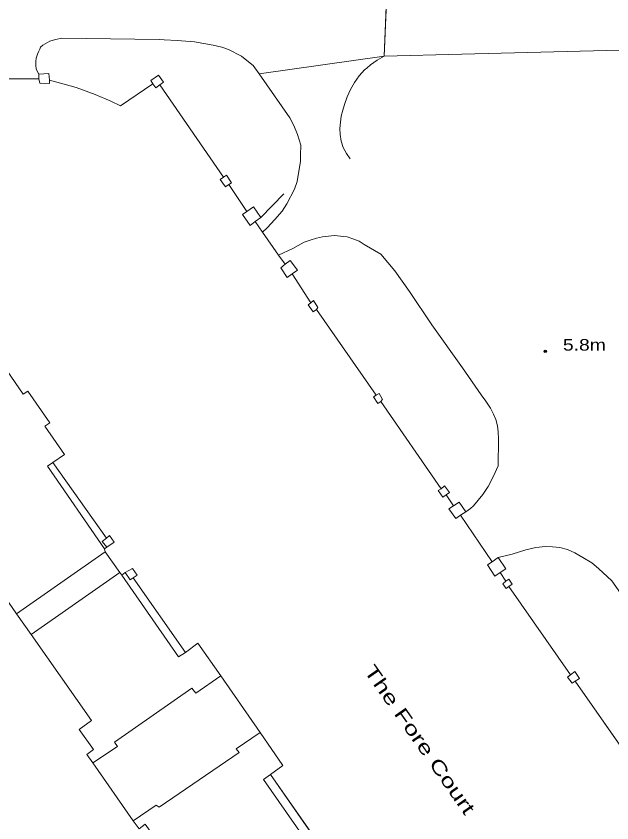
# Model space of a CAD drawing. Extents: x 528790 to 529292, y 179350 to 179856.
# Drawn here: x 529045.4 to 529122.8, y 179668.3 to 179772.9 of the extents above; entities that cross this region are included whole.
import ezdxf

# ---------------------------------------------------------------- set-up
doc = ezdxf.new("R2010")
doc.units = 0
doc.header["$LTSCALE"] = 0.6
doc.header["$PDMODE"] = 32
doc.header["$PDSIZE"] = 0.3
doc.layers.add('1', color=7, linetype='Continuous', lineweight=13)
doc.layers.add('2', color=7, linetype='Continuous', lineweight=13)
doc.layers.add('3', color=7, linetype='Continuous')
doc.layers.add('5', color=7, linetype='Continuous')

msp = doc.modelspace()

# ---------------------------------------------------------------- linework, layer by layer
at = {"layer": '1'}
for points in [[(529093.884, 179783.837), (529093.19, 179767.75), (529103.296, 179768.007), (529128.896, 179768.657), (529142.81, 179769.01), (529140.75, 179788.25)], [(529044.2, 179764.8), (529048.4, 179764.8), (529048.4, 179765.4), (529048.2, 179765.7), (529048.05, 179766.1), (529048, 179766.55), (529048, 179767.05), (529048.05, 179767.5), (529048.2, 179768), (529048.35, 179768.3), (529048.5, 179768.65), (529048.6, 179768.9), (529048.9, 179769.2), (529049.8, 179769.7), (529050.55, 179769.9), (529051.35, 179770.1), (529064, 179769.9), (529064.665, 179769.872), (529066.35, 179769.8), (529068.6, 179769.6), (529071, 179769.2), (529072.15, 179768.9), (529073, 179768.6), (529074.7, 179767.75), (529075.4, 179767.2), (529076.2, 179766.55), (529076.96, 179765.46), (529093.19, 179767.75), (529093.884, 179783.837)], [(529128.896, 179768.657), (529103.296, 179768.007), (529093.19, 179767.75), (529076.96, 179765.46), (529080.95, 179759.75), (529081.5, 179758.75), (529081.95, 179757.6), (529082.4, 179756.2), (529082.35, 179754.9), (529082.35, 179754.388), (529082.35, 179754.1), (529082.05, 179752.3), (529081.9, 179751.5), (529081.55, 179750.5), (529080.55, 179748.6), (529079.95, 179747.65), (529079, 179746.55), (529078, 179745.5), (529077.4, 179744.9), (529079.5, 179741.95), (529081.35, 179742.8), (529082.05, 179743.2), (529082.8, 179743.6), (529083.6, 179743.9), (529084.4, 179744.15), (529085.2, 179744.3), (529086, 179744.4), (529086.75, 179744.5), (529087.55, 179744.4), (529088.4, 179744.3), (529089.15, 179744.05), (529089.95, 179743.75), (529090.6, 179743.3), (529092.75, 179742.05), (529094.6, 179739.9), (529096.5, 179737.2), (529099.4, 179732.9), (529103.35, 179727.3), (529105.8, 179723.8), (529106.4, 179723), (529107, 179722.1), (529107.4, 179721.3), (529107.7, 179720.6), (529107.9, 179719.8), (529108, 179719), (529108.05, 179718.05), (529108, 179714.6), (529107.4, 179713.25), (529106.7, 179711.9), (529106, 179710.9), (529104.8, 179709.4), (529104.4, 179709.05), (529103.8, 179708.65), (529103.1, 179708.2), (529107.2, 179702.15), (529108, 179702.7), (529109.8, 179703.15), (529111.6, 179703.7), (529112.9, 179704), (529114.15, 179704.15), (529115.05, 179704.1), (529116, 179704), (529117, 179703.75), (529117.95, 179703.3), (529119, 179702.7), (529120.15, 179702), (529121, 179701.3), (529122.75, 179699.7), (529130.88, 179688.08)], [(529055.7, 179762.8), (529053.25, 179763.7), (529051.2, 179764.25), (529049.75, 179764.65), (529049.75, 179764.2), (529048.5, 179764.25), (529048.4, 179764.8), (529044.2, 179764.8)], [(529125.85, 179675.4), (529118, 179686.65), (529117.6, 179686.4), (529117, 179687.2), (529117.4, 179687.5), (529109.4, 179698.95), (529109.05, 179698.7), (529108.6, 179699.3), (529109, 179699.65), (529108.25, 179700.75), (529107.55, 179700.3), (529106.6, 179701.75), (529107.2, 179702.15), (529103.1, 179708.2), (529102.5, 179707.75), (529101.6, 179709), (529102.2, 179709.4), (529101.25, 179710.85), (529100.8, 179710.55), (529100.2, 179711.4), (529100.6, 179711.6), (529092.75, 179722.95), (529092.4, 179722.7), (529091.8, 179723.55), (529092.15, 179723.75), (529084.4, 179734.9), (529084, 179734.6), (529083.35, 179735.5), (529083.7, 179735.75), (529081.25, 179739.5), (529080.6, 179739.05), (529079.8, 179740.3), (529080.35, 179740.75), (529079.5, 179741.95), (529077.4, 179744.9), (529076.45, 179746.3), (529075.8, 179745.8), (529074.8, 179747.2), (529075.4, 179747.6), (529073.05, 179751.1), (529072.6, 179750.8), (529071.9, 179751.75), (529072.35, 179752.05), (529064.1, 179764.05), (529063.55, 179763.65), (529063.2, 179764.15), (529059, 179761.3), (529057.75, 179761.9), (529055.7, 179762.8)], [(529039.6, 179703.9), (529045.5, 179695.4), (529057, 179703.45), (529056.9, 179703.85), (529049.5, 179714.55), (529050.2, 179715.05), (529051.7, 179716.05), (529049.15, 179719.75), (529049.8, 179720.2), (529046.95, 179724.3), (529046.35, 179723.9), (529043.7, 179727.75)], [(529043.7, 179727.75), (529046.35, 179723.9), (529046.95, 179724.3), (529049.8, 179720.2), (529049.15, 179719.75), (529051.7, 179716.05), (529050.2, 179715.05), (529057.15, 179705.2), (529057.55, 179705.55), (529058.15, 179704.7), (529057.2, 179704.05), (529056.9, 179703.85), (529057, 179703.45), (529058.9, 179700.75), (529059.15, 179700.4), (529059.6, 179700.75), (529060.55, 179701.3), (529061.15, 179700.4), (529060.65, 179700.05), (529067.4, 179690.4), (529069, 179691.6), (529072, 179687.35), (529077.1, 179680), (529080.05, 179675.7), (529078.45, 179674.55), (529085.2, 179664.9)], [(529061.4, 179667.5), (529060.65, 179668.55), (529055.4, 179676.05), (529054.6, 179677.15), (529055.5, 179677.8), (529053.6, 179680.4), (529055.2, 179681.55), (529047.4, 179692.7), (529045.5, 179695.4), (529039.6, 179703.9)], [(529130.88, 179688.08), (529122.75, 179699.7), (529121, 179701.3), (529120.15, 179702), (529119, 179702.7), (529117.95, 179703.3), (529117, 179703.75), (529116, 179704), (529115.05, 179704.1), (529114.15, 179704.15), (529112.9, 179704), (529111.6, 179703.7), (529109.8, 179703.15), (529108, 179702.7), (529109, 179701.25), (529108.25, 179700.75), (529109, 179699.65), (529109.4, 179699.9), (529109.8, 179699.25), (529109.4, 179698.95), (529117.4, 179687.5), (529117.95, 179687.9), (529118.55, 179687), (529118, 179686.65), (529125.85, 179675.4)]]:
    msp.add_lwpolyline(points, dxfattribs=at)
for points in [[(529076.96, 179765.46), (529076.2, 179766.55), (529075.4, 179767.2), (529074.7, 179767.75), (529073, 179768.6), (529072.15, 179768.9), (529071, 179769.2), (529068.6, 179769.6), (529066.35, 179769.8), (529064.665, 179769.872), (529064, 179769.9), (529051.35, 179770.1), (529050.55, 179769.9), (529049.8, 179769.7), (529048.9, 179769.2), (529048.6, 179768.9), (529048.5, 179768.65), (529048.35, 179768.3), (529048.2, 179768), (529048.05, 179767.5), (529048, 179767.05), (529048, 179766.55), (529048.05, 179766.1), (529048.2, 179765.7), (529048.4, 179765.4), (529049.7, 179765.5), (529049.75, 179764.65), (529051.2, 179764.25), (529053.25, 179763.7), (529055.7, 179762.8), (529057.75, 179761.9), (529059, 179761.3), (529063.2, 179764.15), (529062.9, 179764.6), (529063.9, 179765.3), (529064.55, 179764.4), (529064.1, 179764.05), (529072.35, 179752.05), (529072.75, 179752.3), (529073.4, 179751.3), (529073.05, 179751.1), (529075.4, 179747.6), (529076.25, 179748.2), (529077.2, 179746.8), (529076.45, 179746.3), (529077.4, 179744.9), (529078, 179745.5), (529079, 179746.55), (529079.95, 179747.65), (529080.55, 179748.6), (529081.55, 179750.5), (529081.9, 179751.5), (529082.05, 179752.3), (529082.35, 179754.1), (529082.35, 179754.388), (529082.35, 179754.9), (529082.4, 179756.2), (529081.95, 179757.6), (529081.5, 179758.75), (529080.95, 179759.75)], [(529049.75, 179764.65), (529049.7, 179765.5), (529048.4, 179765.4), (529048.4, 179764.8), (529048.5, 179764.25), (529049.75, 179764.2)], [(529064.1, 179764.05), (529064.55, 179764.4), (529063.9, 179765.3), (529062.9, 179764.6), (529063.2, 179764.15), (529063.55, 179763.65)], [(529073.05, 179751.1), (529073.4, 179751.3), (529072.75, 179752.3), (529072.35, 179752.05), (529071.9, 179751.75), (529072.6, 179750.8)], [(529076.45, 179746.3), (529077.2, 179746.8), (529076.25, 179748.2), (529075.4, 179747.6), (529074.8, 179747.2), (529075.8, 179745.8)], [(529083.7, 179735.75), (529084.05, 179736.05), (529084.6, 179735.15), (529084.4, 179734.9), (529092.15, 179723.75), (529092.55, 179724), (529093, 179723.2), (529092.75, 179722.95), (529100.6, 179711.6), (529101.05, 179712), (529101.7, 179711.15), (529101.25, 179710.85), (529102.2, 179709.4), (529102.95, 179709.9), (529103.8, 179708.65), (529104.4, 179709.05), (529104.8, 179709.4), (529106, 179710.9), (529106.7, 179711.9), (529107.4, 179713.25), (529108, 179714.6), (529108.05, 179718.05), (529108, 179719), (529107.9, 179719.8), (529107.7, 179720.6), (529107.4, 179721.3), (529107, 179722.1), (529106.4, 179723), (529105.8, 179723.8), (529103.35, 179727.3), (529099.4, 179732.9), (529096.5, 179737.2), (529094.6, 179739.9), (529092.75, 179742.05), (529090.6, 179743.3), (529089.95, 179743.75), (529089.15, 179744.05), (529088.4, 179744.3), (529087.55, 179744.4), (529086.75, 179744.5), (529086, 179744.4), (529085.2, 179744.3), (529084.4, 179744.15), (529083.6, 179743.9), (529082.8, 179743.6), (529082.05, 179743.2), (529081.35, 179742.8), (529079.5, 179741.95), (529080.35, 179740.75), (529081, 179741.25), (529081.95, 179740), (529081.25, 179739.5)], [(529081.25, 179739.5), (529081.95, 179740), (529081, 179741.25), (529080.35, 179740.75), (529079.8, 179740.3), (529080.6, 179739.05)], [(529084.4, 179734.9), (529084.6, 179735.15), (529084.05, 179736.05), (529083.7, 179735.75), (529083.35, 179735.5), (529084, 179734.6)], [(529092.75, 179722.95), (529093, 179723.2), (529092.55, 179724), (529092.15, 179723.75), (529091.8, 179723.55), (529092.4, 179722.7)], [(529056.9, 179703.85), (529057.2, 179704.05), (529056.6, 179704.8), (529057.15, 179705.2), (529050.2, 179715.05), (529049.5, 179714.55)], [(529101.25, 179710.85), (529101.7, 179711.15), (529101.05, 179712), (529100.6, 179711.6), (529100.2, 179711.4), (529100.8, 179710.55)], [(529103.1, 179708.2), (529103.8, 179708.65), (529102.95, 179709.9), (529102.2, 179709.4), (529101.6, 179709), (529102.5, 179707.75)], [(529057.15, 179705.2), (529056.6, 179704.8), (529057.2, 179704.05), (529058.15, 179704.7), (529057.55, 179705.55)], [(529045.5, 179695.4), (529047.4, 179692.7), (529058.9, 179700.75), (529057, 179703.45)], [(529108.25, 179700.75), (529109, 179701.25), (529108, 179702.7), (529107.2, 179702.15), (529106.6, 179701.75), (529107.55, 179700.3)], [(529047.4, 179692.7), (529055.2, 179681.55), (529053.6, 179680.4), (529055.5, 179677.8), (529054.6, 179677.15), (529055.4, 179676.05), (529058.6, 179678.2), (529058.2, 179678.75), (529068.25, 179685.75), (529068.75, 179685.1), (529072, 179687.35), (529069, 179691.6), (529067.4, 179690.4), (529066.5, 179689.8), (529059.15, 179700.4), (529058.9, 179700.75)], [(529059.15, 179700.4), (529066.5, 179689.8), (529067.4, 179690.4), (529060.65, 179700.05), (529060.25, 179699.8), (529059.6, 179700.75)], [(529060.65, 179700.05), (529061.15, 179700.4), (529060.55, 179701.3), (529059.6, 179700.75), (529060.25, 179699.8)], [(529109.4, 179698.95), (529109.8, 179699.25), (529109.4, 179699.9), (529109, 179699.65), (529108.6, 179699.3), (529109.05, 179698.7)], [(529072, 179687.35), (529068.75, 179685.1), (529068.25, 179685.75), (529058.2, 179678.75), (529058.6, 179678.2), (529055.4, 179676.05), (529060.65, 179668.55), (529063.6, 179670.55), (529064, 179670.3), (529074.4, 179677.4), (529074, 179677.9), (529077.1, 179680)], [(529118, 179686.65), (529118.55, 179687), (529117.95, 179687.9), (529117.4, 179687.5), (529117, 179687.2), (529117.6, 179686.4)], [(529084.8, 179663.5), (529077.55, 179673.9), (529078.45, 179674.55), (529080.05, 179675.7), (529077.1, 179680), (529074, 179677.9), (529074.4, 179677.4), (529064, 179670.3), (529063.6, 179670.55), (529060.65, 179668.55), (529061.4, 179667.5), (529062.2, 179668.1), (529064.2, 179665.25), (529065.8, 179666.3), (529073.7, 179655.05), (529085.05, 179663.1)], [(529078.45, 179674.55), (529077.55, 179673.9), (529084.8, 179663.5), (529085.35, 179663.9), (529084.8, 179664.65), (529085.2, 179664.9)]]:
    msp.add_lwpolyline(points, close=True, dxfattribs=at)
at = {"layer": '2'}
for p, q in [((529093.19, 179767.75), (529093.884, 179783.837)), ((529093.19, 179767.75), (529076.96, 179765.46)), ((529044.2, 179764.8), (529048.4, 179764.8)), ((529048.4, 179764.8), (529048.4, 179765.4)), ((529064.1, 179764.05), (529072.35, 179752.05)), ((529073.05, 179751.1), (529075.4, 179747.6)), ((529077.2, 179746.8), (529080.164, 179749.87)), ((529076.45, 179746.3), (529077.2, 179746.8)), ((529076.45, 179746.3), (529077.4, 179744.9)), ((529077.4, 179744.9), (529079.5, 179741.95)), ((529079.5, 179741.95), (529080.35, 179740.75)), ((529081.25, 179739.5), (529083.7, 179735.75)), ((529084.4, 179734.9), (529092.15, 179723.75)), ((529092.75, 179722.95), (529100.6, 179711.6)), ((529050.2, 179715.05), (529057.15, 179705.2)), ((529101.25, 179710.85), (529102.2, 179709.4)), ((529103.8, 179708.65), (529103.1, 179708.2)), ((529103.1, 179708.2), (529107.2, 179702.15)), ((529057.2, 179704.05), (529056.9, 179703.85)), ((529056.9, 179703.85), (529057, 179703.45)), ((529045.5, 179695.4), (529057, 179703.45)), ((529057, 179703.45), (529058.9, 179700.75)), ((529107.2, 179702.15), (529108, 179702.7)), ((529047.4, 179692.7), (529058.9, 179700.75)), ((529058.9, 179700.75), (529059.15, 179700.4)), ((529059.6, 179700.75), (529059.15, 179700.4)), ((529108.25, 179700.75), (529109, 179699.65)), ((529067.4, 179690.4), (529060.65, 179700.05)), ((529109.4, 179698.95), (529117.4, 179687.5)), ((529047.4, 179692.7), (529045.5, 179695.4)), ((529072, 179687.35), (529077.1, 179680)), ((529118, 179686.65), (529125.85, 179675.4)), ((529060.65, 179668.55), (529055.4, 179676.05)), ((529078.45, 179674.55), (529085.2, 179664.9))]:
    msp.add_line(p, q, dxfattribs=at)
for points in [[(529048.4, 179765.4), (529048.2, 179765.7), (529048.05, 179766.1), (529048, 179766.55), (529048, 179767.05), (529048.05, 179767.5), (529048.2, 179768), (529048.35, 179768.3), (529048.5, 179768.65), (529048.6, 179768.9), (529048.9, 179769.2), (529049.8, 179769.7), (529050.55, 179769.9), (529051.35, 179770.1), (529064, 179769.9), (529064.665, 179769.872)], [(529064.665, 179769.872), (529066.35, 179769.8), (529068.6, 179769.6), (529071, 179769.2), (529072.15, 179768.9), (529073, 179768.6), (529074.7, 179767.75), (529075.4, 179767.2), (529076.2, 179766.55), (529076.96, 179765.46)], [(529142.81, 179769.01), (529128.896, 179768.657), (529103.296, 179768.007), (529093.19, 179767.75)], [(529088.79, 179754.43), (529088.3, 179755.14), (529087.9, 179755.91), (529087.62, 179756.74), (529087.48, 179757.58), (529087.46, 179758.38), (529087.52, 179759.17), (529087.64, 179759.96), (529087.82, 179760.74), (529088.05, 179761.5), (529088.41, 179762.48), (529088.85, 179763.43), (529089.37, 179764.34), (529089.97, 179765.2), (529090.66, 179765.96), (529090.95, 179766.21), (529091.44, 179766.65), (529092.29, 179767.25), (529093.19, 179767.75)], [(529048.4, 179765.4), (529049.7, 179765.5), (529049.75, 179764.65)], [(529049.75, 179764.65), (529049.75, 179764.2), (529048.5, 179764.25), (529048.4, 179764.8)], [(529049.75, 179764.65), (529051.2, 179764.25), (529053.25, 179763.7), (529055.7, 179762.8), (529057.75, 179761.9), (529059, 179761.3), (529063.2, 179764.15)], [(529063.2, 179764.15), (529062.9, 179764.6), (529063.9, 179765.3), (529064.55, 179764.4), (529064.1, 179764.05)], [(529076.96, 179765.46), (529080.95, 179759.75), (529081.5, 179758.75), (529081.95, 179757.6), (529082.4, 179756.2), (529082.35, 179754.9), (529082.35, 179754.388)], [(529064.1, 179764.05), (529063.55, 179763.65), (529063.2, 179764.15)], [(529082.35, 179754.388), (529082.35, 179754.1), (529082.05, 179752.3), (529081.9, 179751.5), (529081.55, 179750.5), (529080.55, 179748.6), (529079.95, 179747.65), (529079, 179746.55), (529078, 179745.5), (529077.4, 179744.9)], [(529073.05, 179751.1), (529072.6, 179750.8), (529071.9, 179751.75), (529072.35, 179752.05)], [(529073.05, 179751.1), (529073.4, 179751.3), (529072.75, 179752.3), (529072.35, 179752.05)], [(529077.2, 179746.8), (529076.25, 179748.2), (529075.4, 179747.6)], [(529076.45, 179746.3), (529075.8, 179745.8), (529074.8, 179747.2), (529075.4, 179747.6)], [(529079.5, 179741.95), (529081.35, 179742.8), (529082.05, 179743.2), (529082.8, 179743.6), (529083.6, 179743.9), (529084.4, 179744.15), (529085.2, 179744.3), (529086, 179744.4), (529086.75, 179744.5), (529087.55, 179744.4), (529088.4, 179744.3), (529089.15, 179744.05), (529089.95, 179743.75), (529090.6, 179743.3), (529092.75, 179742.05), (529094.6, 179739.9), (529096.5, 179737.2), (529099.4, 179732.9), (529103.35, 179727.3), (529105.8, 179723.8), (529106.4, 179723), (529107, 179722.1), (529107.4, 179721.3), (529107.7, 179720.6), (529107.9, 179719.8), (529108, 179719), (529108.05, 179718.05), (529108, 179714.6), (529107.4, 179713.25), (529106.7, 179711.9), (529106, 179710.9), (529104.8, 179709.4), (529104.4, 179709.05), (529103.8, 179708.65)], [(529081.25, 179739.5), (529080.6, 179739.05), (529079.8, 179740.3), (529080.35, 179740.75)], [(529081.25, 179739.5), (529081.95, 179740), (529081, 179741.25), (529080.35, 179740.75)], [(529084.4, 179734.9), (529084, 179734.6), (529083.35, 179735.5), (529083.7, 179735.75)], [(529084.4, 179734.9), (529084.6, 179735.15), (529084.05, 179736.05), (529083.7, 179735.75)], [(529024.2, 179714.15), (529027.75, 179716.6), (529027.7, 179717.15), (529038, 179724.3), (529038.5, 179724.15), (529043.7, 179727.75), (529046.35, 179723.9), (529046.95, 179724.3), (529049.8, 179720.2), (529049.15, 179719.75), (529051.7, 179716.05), (529050.2, 179715.05)], [(529092.75, 179722.95), (529092.4, 179722.7), (529091.8, 179723.55), (529092.15, 179723.75)], [(529092.75, 179722.95), (529093, 179723.2), (529092.55, 179724), (529092.15, 179723.75)], [(529050.2, 179715.05), (529049.5, 179714.55), (529056.9, 179703.85)], [(529101.25, 179710.85), (529100.8, 179710.55), (529100.2, 179711.4), (529100.6, 179711.6)], [(529101.25, 179710.85), (529101.7, 179711.15), (529101.05, 179712), (529100.6, 179711.6)], [(529103.1, 179708.2), (529102.5, 179707.75), (529101.6, 179709), (529102.2, 179709.4)], [(529103.8, 179708.65), (529102.95, 179709.9), (529102.2, 179709.4)], [(529057.2, 179704.05), (529056.6, 179704.8), (529057.15, 179705.2)], [(529057.15, 179705.2), (529057.55, 179705.55), (529058.15, 179704.7), (529057.2, 179704.05)], [(529045.5, 179695.4), (529039.6, 179703.9), (529038.85, 179703.45), (529036.4, 179701.7), (529010.8, 179683.9), (529011.4, 179683.1), (529010, 179682.1)], [(529130.88, 179688.08), (529122.75, 179699.7), (529121, 179701.3), (529120.15, 179702), (529119, 179702.7), (529117.95, 179703.3), (529117, 179703.75), (529116, 179704), (529115.05, 179704.1), (529114.15, 179704.15), (529112.9, 179704), (529111.6, 179703.7), (529109.8, 179703.15), (529108, 179702.7)], [(529108.25, 179700.75), (529107.55, 179700.3), (529106.6, 179701.75), (529107.2, 179702.15)], [(529108, 179702.7), (529109, 179701.25), (529108.25, 179700.75)], [(529059.6, 179700.75), (529060.55, 179701.3), (529061.15, 179700.4), (529060.65, 179700.05)], [(529060.65, 179700.05), (529060.25, 179699.8), (529059.6, 179700.75)], [(529059.15, 179700.4), (529066.5, 179689.8), (529067.4, 179690.4)], [(529109.4, 179698.95), (529109.05, 179698.7), (529108.6, 179699.3), (529109, 179699.65)], [(529109.4, 179698.95), (529109.8, 179699.25), (529109.4, 179699.9), (529109, 179699.65)], [(529055.4, 179676.05), (529054.6, 179677.15), (529055.5, 179677.8), (529053.6, 179680.4), (529055.2, 179681.55), (529047.4, 179692.7)], [(529067.4, 179690.4), (529069, 179691.6), (529072, 179687.35)], [(529055.4, 179676.05), (529058.6, 179678.2), (529058.2, 179678.75), (529068.25, 179685.75), (529068.75, 179685.1), (529072, 179687.35)], [(529118, 179686.65), (529117.6, 179686.4), (529117, 179687.2), (529117.4, 179687.5)], [(529118, 179686.65), (529118.55, 179687), (529117.95, 179687.9), (529117.4, 179687.5)], [(529060.65, 179668.55), (529063.6, 179670.55), (529064, 179670.3), (529074.4, 179677.4), (529074, 179677.9), (529077.1, 179680)], [(529077.1, 179680), (529080.05, 179675.7), (529078.45, 179674.55)], [(529078.45, 179674.55), (529077.55, 179673.9), (529084.8, 179663.5)], [(529073.7, 179655.05), (529065.8, 179666.3), (529064.2, 179665.25), (529062.2, 179668.1), (529061.4, 179667.5), (529060.65, 179668.55)]]:
    msp.add_lwpolyline(points, dxfattribs=at)
at = {"layer": '3'}
msp.add_point((529114.1, 179729.45), dxfattribs=at)

# ---------------------------------------------------------------- texts
at = {"layer": '5', "width": 1.25}
msp.add_text('5.8m', height=1.5, dxfattribs=at).set_placement((529116.4, 179729.55))
at = {"layer": '5', "width": 1.45}
msp.add_text('The Fore Court', height=1.75, rotation=305, dxfattribs=at).set_placement((529090.5, 179688))

doc.saveas('drawing.dxf')
